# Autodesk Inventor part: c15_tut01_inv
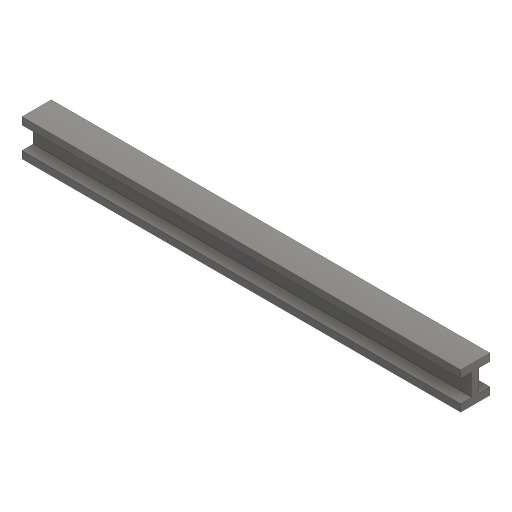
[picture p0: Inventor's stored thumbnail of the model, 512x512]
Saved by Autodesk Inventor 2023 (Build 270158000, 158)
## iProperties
Created: 2017-05
Part Number: c15_tut01_inv
Material: Steel, Alloy
Document SubType Name: Modeling
Designer: CADCIM 00
Mass: 637.725 g
Surface Area: 365.5 cm^2
Volume: 82.5 cm^3
Density: 7.73 g/cm^3
Appearance: Semi-Polished
Author: CADCIM 00
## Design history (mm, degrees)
sketch "Sketch1"
  geometry: L1 (-10, 25)-(10, 25); L2 (10, 25)-(10, 20); L3 (10, 20)-(2.5, 20); L4 (2.5, 20)-(2.5, 5); L5 (2.5, 5)-(10, 5); L6 (10, 5)-(10, 0); L7 (10, 0)-(-10, 0); L8 (-10, 0)-(-10, 5); L9 (-10, 5)-(-2.5, 5); L10 (-2.5, 5)-(-2.5, 20); L11 (-2.5, 20)-(-10, 20); L12 (-10, 25)-(-10, 20); 2 further points
  constraints: 24 end point, 8 perpendicular, 7 point on line, 2 collinear, 1 coincident, 1 horizontal, 1 midpoint
  dimensions: "d0" = 20 distance of L1.start L1.end; "d1" = 5 distance between parallel lines of L3 L1; "d2" = 15 distance between parallel lines of L5 L3; "d3" = 5 distance between parallel lines of L4 L10
extrude "Extrusion1" new body sketch "Sketch1" distance "d4" = 300; taper "d5" = 0 deg
body "Solid1"
other parameters: "sa_0" = 0, "sa_1" = 0, "sa_2" = -1000000
